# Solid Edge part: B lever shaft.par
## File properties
Author: vinurabandara
Template: iso metric part.par
Last saved by: Nimesh.N
Revision: 12
Application: Solid Edge
Density: 7833.000 kg/m^3
Accuracy: 0.990
Username: Nimesh.N
Material: Steel
Face Style: Steel
Fill Style: ANSI32(Steel)
Virtual Style: Machined steel
Grouping: Metals\Steel
LibraryName: Materials
Coef. of Thermal Exp: 1.3e-05
Thermal Conductivity: 32.0
Specific Heat: 481.0
Modulus of Elasticity: 199947953000.0
Poisson's Ratio: 0.29
Yield Stress: 262000766.0
Ultimate Stress: 358527364.0
Elongation: 0.0
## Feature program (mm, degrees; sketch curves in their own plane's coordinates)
sketch for "unnamed Protrusion 1" plane through (0, 0, 0) normal (0, -1, 0) x-axis (1, 0, 0)
  circle centre (0, 0) radius 7.5
extrude "unnamed Protrusion 1" add finite 1150 along +normal
sketch for "ExtrudedProtrusion_4" plane through (0, -190, 0) normal (0, -1, 0) x-axis (1, 0, 0)
  circle centre (0, 0) radius 9.5
extrude "ExtrudedProtrusion_4" add finite 10 along -normal  Profile_Plane1_Distance = 190 mm
sketch for "ExtrudedProtrusion_5" plane through (0, 0, 0) normal (0, 1, 0) x-axis (0, 0, -1)
extrude "ExtrudedProtrusion_5" add finite 5 along +normal
sketch for "ExtrudedProtrusion_6" plane through (0, -1150, 0) normal (0, -1, 0) x-axis (1, 0, 0)
extrude "ExtrudedProtrusion_6" add finite 5 along +normal
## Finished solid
Body 1: solid body, 7 faces, 6 edges, 0 vertices.
  Faces by surface: plane 4, cylinder 3
  Edges by curve: circle 6
Bounding box of the edges (mm): 19.000 x 1160.000 x 19.000, from (-9.5, -1155, -9.5) to (9.5, 5, 9.5).
Cylindrical faces by radius (mm): R7.5 x2, R9.5 x1
Planar faces by outward normal: +y 2, -y 2
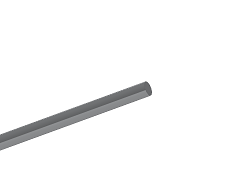
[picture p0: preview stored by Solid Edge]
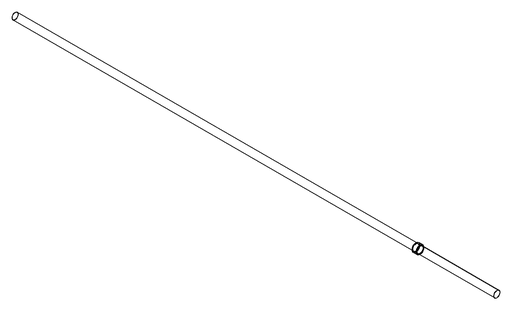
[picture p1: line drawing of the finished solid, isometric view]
